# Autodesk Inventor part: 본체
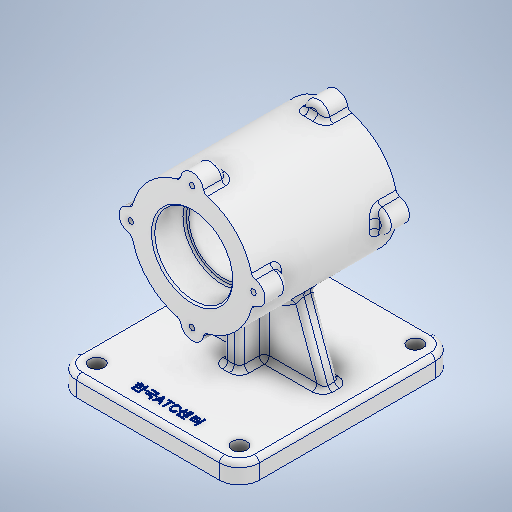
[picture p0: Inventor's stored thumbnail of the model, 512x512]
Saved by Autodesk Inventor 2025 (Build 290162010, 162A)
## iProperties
Created: 2024-08
Part Number: 본체
Material: 알루미늄 6061
Document SubType Name: Modeling
Designer: 학생
Density: 2.7 g/cm^3
Appearance: 알루미늄 - 평지
Mass: 1215.39 g
Surface Area: 796.917 cm^2
Volume: 450.145 cm^3
Author: 학생
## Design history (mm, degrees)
sketch "스케치1"
  geometry: C1 r 37 at (0, 0); 1 further point
  constraints: 1 centre point, 1 coincident
  dimensions: "d0" = 74 diameter of C1
extrude "돌출1" new body sketch "스케치1" stored distance "d1" = 87; taper "d2" = 0 deg
sketch "스케치2"
  geometry: L1 (-90.461, 0)-(90.461, 0); L2 (0, 60.308)-(0, -67.296); C1 r 7 at (0, 37); C2 r 7 at (-37, 0); C3 r 7 at (0, -37); C4 r 7 at (37, 0); 2 further points
  constraints: 4 centre point, 4 end point, 2 point on line, 1 horizontal, 1 midpoint, 1 vertical, 1 vertical alignment, 10 other
  dimensions: "d3" = 14 diameter of C1; "d6" = 360 deg dimension on point (0, 0) C1.centre (derived)
extrude "돌출2" join sketch "스케치2" distance "d8" = 14; taper "d9" = 0 deg
node "작업 평면1"
sketch "스케치3"
  geometry: L1 (55, 70)-(-55, 70); L2 (-55, 70)-(-55, -60); L3 (-55, -60)-(55, -60); L4 (55, -60)-(55, 70); L5 (55, 70)-(-55, -60); L6 (-55, 70)-(55, -60); 2 further points
  constraints: 12 end point, 2 midpoint, 2 parallel, 1 horizontal, 1 perpendicular, 1 vertical alignment
  dimensions: "d11" = 130 distance of L3.end L1.start; "d12" = 110 distance of L2.end L3.end; "d30" = 70 distance from line of L1 point (0, 0)
extrude "돌출3" join sketch "스케치3" distance "d13" = 12; taper "d14" = 0 deg
sketch "스케치5"
  geometry: L1 (-5, 20)-(5, 20); L2 (5, 20)-(5, -20); L3 (5, -20)-(-5, -20); L4 (-5, -20)-(-5, 20); L5 (-55, -70)-(55, -70) reference; 2 further points
  constraints: 8 end point, 2 parallel, 1 horizontal, 1 midpoint, 1 perpendicular, 1 vertical alignment
  dimensions: "d22" = 10 distance of L1.start L1.end; "d23" = 40 distance of L1.end L2.end; "d24" = 50 distance between parallel lines of L5 L3
extrude "돌출5" join sketch "스케치5" stored distance "d25" = 10; taper "d26" = 0 deg
sketch "스케치7"
  geometry: L1 (-22.946, -20.396)-(-41, -70); L2 (55, -70)-(-55, -70) reference; L3 (41, -70)-(22.946, -20.396); L4 (22.946, -20.396)-(-22.946, -20.396); L5 (0, 11.975)-(0, -94.484); L6 (-55, -82)-(-55, -70) reference; 2 further points
  constraints: 8 end point, 3 point on line, 1 midpoint, 1 parallel, 1 vertical, 1 other
  dimensions: "d31" = 110 deg angle of L2 L1; "d32" = 14 horizontal distance of point (-55, -76) L1.end; "d33" = 49.60432 distance between parallel lines of L2 L4
extrude "돌출6" join sketch "스케치7" stored distance "d34" = 10; taper "d35" = 0 deg
sketch "스케치8"
  geometry: A1 r 37 centre (0, 0) between (36.338, 6.969) and (6.969, 36.338) reference; 2 further points
  constraints: 1 coincident
hole "구멍1" sketch "스케치8" at (0, 0) diameter "d36" = 47; stored, may be unused: countersink angle "d40" = 90 deg, drill point angle "d42" = 0 deg; dims "d37" = 6, "d38" = 4, "d39" = 2, "d41" = 19
sketch "스케치9"
  geometry: A1 r 37 centre (0, 0) between (36.338, 6.969) and (6.969, 36.338) reference; 2 further points
  constraints: 1 coincident
hole "구멍2" sketch "스케치9" at (0, 0) diameter "d43" = 47; stored, may be unused: countersink angle "d47" = 90 deg, drill point angle "d49" = 0 deg; dims "d44" = 6, "d45" = 4, "d46" = 2, "d48" = 19
sketch "스케치10"
  geometry: C1 r 23.5 at (0, 0) reference; 2 further points
  constraints: 1 coincident
hole "구멍3" sketch "스케치10" at (0, 0) diameter "d50" = 42; stored, may be unused: countersink angle "d54" = 90 deg, drill point angle "d56" = 0 deg; dims "d51" = 6, "d52" = 4, "d53" = 2, "d55" = 19
fillet "모깎기1" dims "d57" = 12
sketch "스케치11"
  geometry: A1 r 12 centre (43, -58) between (43, -70) and (55, -58) reference; A2 r 12 centre (-43, -58) between (-55, -58) and (-43, -70) reference; A3 r 12 centre (43, 48) between (55, 48) and (43, 60) reference; A4 r 12 centre (-43, 48) between (-43, 60) and (-55, 48) reference; 5 further points
  constraints: 4 coincident
hole "구멍4" sketch "스케치11" at (43, -58), (-43, -58), (43, 48), (-43, 48) diameter "d58" = 9; stored, may be unused: countersink angle "d62" = 90 deg, drill point angle "d64" = 0 deg; dims "d59" = 6, "d60" = 4, "d61" = 2, "d63" = 8
sketch "스케치12" dims "d65" = 74
  geometry: L1 (0, 71.26)-(0, -102.389); L2 (-89.397, 0)-(110.75, 0); 3 further points
  constraints: 4 end point, 3 point on line, 1 coincident, 1 horizontal, 1 vertical, 1 vertical alignment, 2 other
hole "구멍5" sketch "스케치12" at (0, 37) diameter "d66" = 3.242; stored, may be unused: countersink angle "d70" = 90 deg, drill point angle "d72" = 118 deg; dims "d67" = 8, "d68" = 4, "d69" = 2, "d71" = 10
fillet "모깎기2" dims "d76" = 3
fillet "모깎기3" dims "d77" = 3
fillet "모깎기4" dims "d78" = 3
fillet "모깎기5" dims "d79" = 3
fillet "모깎기6" dims "d80" = 3
fillet "모깎기7" dims "d81" = 1
chamfer "모따기1" distance "d82" = 1; stored, may be unused: second distance "d83" = 2, angle "d84" = 45 deg
sketch "스케치13"
  geometry: 2 further points
  constraints: 1 vertical alignment, 1 other
  dimensions: "d85" = 58 distance of point (0, 0) point (0, -58)
feature "엠보싱1" sketch "스케치13" dims "d86" = 0.5, "d87" = 0
feature "ˣ耀˥耀˧耀˩耀˫耀˭耀˯耀˱耀" dims "d0" = 74, "d1" = 87, "d2" = 0, "d3" = 14, "d4" = 40, "d6" = 360 deg (derived), "d8" = 14, "d9" = 0, "d10" = -82, "d11" = 130, "d12" = 110, "d13" = 12, "d14" = 0, "d22" = 10, "d23" = 40, "d24" = 50, "d25" = 10, "d26" = 0, "d30" = 70, "d31" = 110 deg, "d32" = 14, "d33" = 49.60432, "d34" = 10, "d35" = 0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
node "솔리드1"
mirror "미러1"
pattern_circular "원형 패턴1" dims angle "d74" = 360 deg
mirror "미러2"
node "스케치 - 원형 패턴1" dims "d6" = 360 deg (derived)
feature "A9D066F2-1C7D-4E18-AEED-F7BC21143FA4" dims "d36" = 47, "d37" = 6, "d38" = 4, "d39" = 2, "d40" = 90 deg, "d41" = 19, "d42" = 0
